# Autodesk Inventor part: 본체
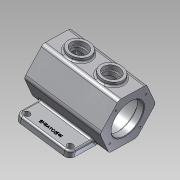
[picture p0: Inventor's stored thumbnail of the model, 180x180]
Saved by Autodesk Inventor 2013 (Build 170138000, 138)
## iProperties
Created: 2021-06
Part Number: 본체
Material: 알루미늄 6061
Document SubType Name: Modeling
Designer: hana
Density: 2.71 g/cm^3
Mass: 1501.03 g
Surface Area: 1103.25 cm^2
Volume: 553.887 cm^3
Author: hana
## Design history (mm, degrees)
sketch "스케치1" dims "d0" = 105
  geometry: L1 (52.5, 0)-(26.25, -45.466); L2 (26.25, -45.466)-(-26.25, -45.466); L3 (-26.25, -45.466)-(-52.5, 0); L4 (-52.5, 0)-(-26.25, 45.466); L5 (-26.25, 45.466)-(26.25, 45.466); L6 (26.25, 45.466)-(52.5, 0); 3 further points
  constraints: 12 end point, 2 coincident, 2 horizontal alignment, 15 other
extrude "돌출1" new body sketch "스케치1" stored distance "d1" = 140; taper "d2" = 0 deg
node "작업 평면1"
sketch "스케치2"
  geometry: L1 (73.5, 0)-(-73.5, 0) reference; L2 (0, -98)-(0, 98) reference; L3 (-107.676, -71.784)-(107.676, 71.784); L4 (107.676, -71.784)-(-107.676, 71.784); L5 (-75, -55)-(75, -55); L6 (75, -55)-(75, 45); L7 (75, 45)-(-75, 45); L8 (-75, 45)-(-75, -55); L9 (26.25, -70)-(-26.25, -70) reference; L10 (-26.25, 70)-(26.25, 70) reference; 1 further point
  constraints: 12 end point, 2 midpoint, 2 parallel, 1 horizontal, 1 perpendicular, 1 other
  dimensions: "d7" = 100 distance between parallel lines of L7 L5; "d9" = 150 distance between parallel lines of L6 L8; "d107" = 25 distance between parallel lines of L7 L10
extrude "돌출2" join sketch "스케치2" distance "d11" = 12; taper "d12" = 0 deg
node "작업 평면2"
sketch "스케치4"
  geometry: L1 (105, 0)-(-105, 0) reference; L2 (0, -98)-(0, 98) reference; L3 (-26.25, 70)-(26.25, 70) reference; C1 r 20 at (0, 30); C2 r 20 at (0, -30); 1 further point
  constraints: 2 centre point, 2 point on line
  dimensions: "d17" = 40 diameter of C1; "d18" = 40 diameter of C2; "d19" = 60 distance of C2.centre C1.centre; "d20" = 40 distance from line of C1.centre L3
extrude "돌출4" join sketch "스케치4" stored distance "d21" = 12; taper "d22" = 0 deg
sketch "스케치5"
  geometry: L1 (0, 128)-(0, -68) reference; L2 (-105, 30)-(105, 30) reference; C1 r 20 at (0, 0) reference; C2 r 20 at (0, 60) reference; C3 r 15 at (0, 0); C4 r 15 at (0, 60); 1 further point
  constraints: 2 centre point, 2 coincident
  dimensions: "d23" = 30 diameter of C3; "d24" = 30 diameter of C4
extrude "돌출5" cut sketch "스케치5" distance "d25" = 8; taper "d26" = 0 deg
fillet "모깎기1" dims "d33" = 10
sketch "스케치9"
  geometry: C1 r 5.5 at (65, -35); C2 r 5.5 at (65, 45); A1 r 10 centre (65, 45) between (75, 45) and (65, 55) reference; A2 r 10 centre (65, -35) between (65, -45) and (75, -35) reference; 1 further point
  constraints: 2 centre point, 2 coincident
  dimensions: "d34" = 11 diameter of C1; "d35" = 11 diameter of C2
extrude "돌출8" cut sketch "스케치9" stored distance "d36" = 8; taper "d37" = 0 deg
sketch "스케치10"
  geometry: L1 (0, -98)-(0, 98) reference; L2 (-70.5, 0)-(73, 0) reference; L3 (45.466, 70)-(0, 70) reference; L4 (0, 70)-(30, 70); L5 (30, 70)-(30, 58); L6 (30, 58)-(37.5, 58); L7 (37.5, 58)-(37.5, -58); L8 (37.5, -58)-(30, -58); L9 (0, -70)-(45.466, -70) reference; L10 (30, -58)-(30, -70); L11 (30, -70)-(0, -70); L12 (0, 70)-(0, -70); 1 further point
  constraints: 16 end point, 4 perpendicular, 2 parallel, 2 point on line, 1 collinear
  dimensions: "d38" = 12 distance between parallel lines of L6 L3; "d39" = 12 distance between parallel lines of L9 L8; "d40" = 60 diameter of L5 L1; "d41" = 60 diameter of L10 L1; "d42" = 75 diameter of L7 L1
revolve "회전1" sketch "스케치10" stored, may be unused: angle "d43" = 90 deg
sketch "스케치11"
  geometry: C1 r 15 at (0, 0) reference; C2 r 12.5 at (0, 0); 1 further point
  constraints: 1 centre point, 1 coincident
  dimensions: "d44" = 25 diameter of C2
extrude "돌출9" cut sketch "스케치11" stored distance "d45" = 8; taper "d46" = 0 deg
sketch "스케치12"
  geometry: C1 r 15 at (0, 0) reference; C2 r 12.5 at (0, 0); 1 further point
  constraints: 1 centre point, 1 coincident
  dimensions: "d47" = 25 diameter of C2
extrude "돌출10" cut sketch "스케치12" stored distance "d48" = 8; taper "d49" = 0 deg
sketch "스케치13" dims "d50" = 80
  geometry: L1 (0, 0)-(28.284, 28.284); L2 (-105, 0)-(105, 0) reference; C1 r 30 at (0, 0) reference; 1 further point
  constraints: 2 coincident, 2 end point, 3 other
  dimensions: "d51" = 45 deg angle of L1 L2
hole "구멍1" sketch "스케치13" at (28.284, 28.284) diameter "d53" = 3.242; stored, may be unused: countersink angle "d57" = 90 deg, drill point angle "d59" = 118 deg; dims "d54" = 8, "d55" = 4, "d56" = 2, "d58" = 10
fillet "모깎기2" dims "d63" = 5
fillet "모깎기3" dims "d64" = 8
fillet "모깎기4" dims "d65" = 3
fillet "모깎기5" dims "d66" = 3
chamfer "모따기1" distance "d67" = 1; stored, may be unused: second distance "d68" = 2, angle "d69" = 45 deg
sketch "스케치14"
  geometry: L1 (-65, -45)-(-32.293, -45) reference; L2 (-75, 45)-(-75, -35) reference; 2 further points
  constraints: 1 other
  dimensions: "d70" = 50 distance from line of point (-61, 5) L1; "d71" = 14 distance from line of point (-61, 5) L2
feature "엠보싱1" sketch "스케치14" dims "d11" = 12, "d12" = 0, "d72" = 0.5, "d73" = 0
sketch "스케치17" dims "d96" = 80
  geometry: C1 r 31 at (0, 0) reference; 2 further points
  constraints: 2 horizontal alignment, 1 coincident, 2 other
hole "구멍4" sketch "스케치17" at (40, 0) diameter "d97" = 3.242; stored, may be unused: countersink angle "d101" = 90 deg, drill point angle "d103" = 118 deg; dims "d98" = 8, "d99" = 4, "d100" = 2, "d102" = 10
chamfer "모따기2" distance "d108" = 1; stored, may be unused: second distance "d109" = 2, angle "d110" = 45 deg
node "솔리드1"
mirror "대칭1"
pattern_circular "원형 패턴1" dims angle "d61" = 360 deg
pattern_circular "원형 패턴2" dims angle "d105" = 360 deg
node "투영된 루프1"
other parameters: "d16" = 52.5
